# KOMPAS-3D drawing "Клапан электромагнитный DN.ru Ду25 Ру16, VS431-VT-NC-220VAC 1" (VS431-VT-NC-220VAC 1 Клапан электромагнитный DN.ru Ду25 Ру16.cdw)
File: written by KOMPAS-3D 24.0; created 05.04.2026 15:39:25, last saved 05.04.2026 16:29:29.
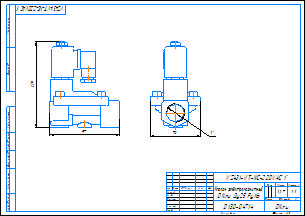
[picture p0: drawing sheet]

Document properties: c3d_UniqueCompID: ef56311e-7521-43dc-8291-0e6108b3d81d; Автор: artio; Класс точности: c; Знак неуказанной шероховатости: Шероховатость не задана; Рассекать на разрезах: Да; c3d_UniqueCompID: ef56311e-7521-43dc-8291-0e6108b3d81d; Автор: artio; Класс точности: c; Знак неуказанной шероховатости: Шероховатость не задана; Рассекать на разрезах: Да; Автор: artio; Форматы листов документа: A3; Полное имя файла: VS431-VT-NC-220VAC 1 Клапан электромагнитный DN.ru Ду25 Ру16.m3d; Масса: 1.267; Наименование: Клапан электромагнитный DN.ru Ду25 Ру16; Количество листов документа: 1; Примечание: D130-04714

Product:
- Body: Тело 1  | qty 1
    Масса: 1.729172
- Part/product: Клапан электромагнитный DN.ru Ду25 Ру16  | designation VS431-VT-NC-220VAC 1
    Масса: 1.267
    Раздел спецификации: Прочие изделия
    Примечание: D130-04714
    additional columns: ef56311e-7521-43dc-8291-0e6108b3d81d; artio; c; Шероховатость не задана; Да

Views: Вид 1, Спереди, Проекционный вид 2
Referenced files in C:\Users\artio\OneDrive\Рабочий стол\Клапан электромагнитный DN.ru\VS431\VS431-ET-NC\: VS431-ET-NC-220VAC 3-4 Клапан электромагнитный DN.ru Ду20 Ру16.m3d, VS431-ET-NC-220VAC 3-4 Клапан электромагнитный DN.ru Ду20 Ру16.cdw
Referenced files in C:\Users\artio\OneDrive\Рабочий стол\Клапан электромагнитный DN.ru\VS431\VS431-VT-NC\: VS431-VT-NC-220VAC 1 Клапан электромагнитный DN.ru Ду25 Ру16.m3d
Referenced files in C:\Users\artio\OneDrive\Рабочий стол\Клапан электромагнитный DN.ru\VS431\VS431-VT-NC\VS431-VT-NC-220VAC\Ду25\: VS431-VT-NC-220VAC 1 Клапан электромагнитный DN.ru Ду25 Ру16.m3d
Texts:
  VS431-VT-NC-220VAC 1
  Клапан электромагнитный
  DN.ru Ду25 Ру16
  VS431-VT-NC-220VAC 1"
  VS431-VT-NC-220VAC 1"-
  Клапан электромагнитный DN.ru Ду25 Ру16
  VS431-VT-NC-220VAC 1 Клапан электромагнитный DN.ru Ду25 Ру16
Dimensions and other numbers on the sheet: 0; 3; 2; 4; 70; 97; 119; 1:1; 1; 1,27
